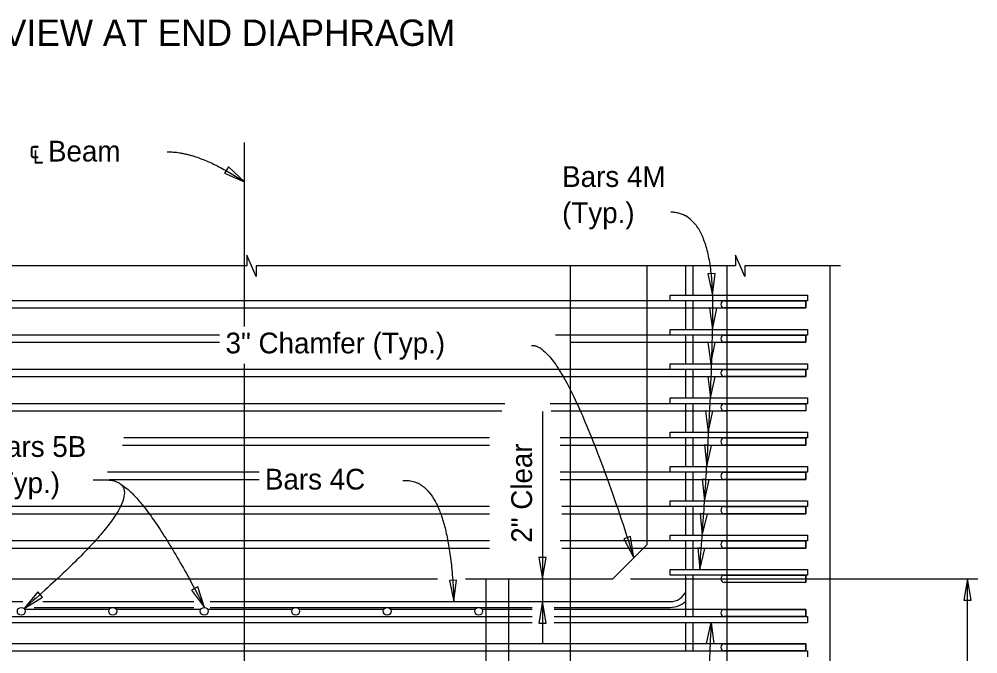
# Model space of a CAD drawing. Extents: x 120700.3 to 120754.4, y 120608.4 to 120631.3.
# Drawn here: x 120705.72 to 120712.71, y 120614.85 to 120619.48 of the extents above; entities that cross this region are included whole.
import ezdxf

# ---------------------------------------------------------------- set-up
doc = ezdxf.new("R2010")
doc.units = 0
for name, color, linetype in [('BeamConc', 7, 'Continuous'), ('BeamConc_h', 7, 'Continuous'), ('CL_Major', 7, 'Continuous'), ('Dimension', 7, 'Continuous'), ('Miscellaneous', 7, 'Continuous'), ('Rebar', 7, 'Continuous'), ('Rebar_h', 7, 'Continuous'), ('TextStructures', 7, 'Continuous')]:
    doc.layers.add(name, color=color, linetype=linetype)

msp = doc.modelspace()

# ---------------------------------------------------------------- linework, layer by layer
at = {"layer": 'BeamConc'}
for p, q in [((120710.3004, 120615.6485), (120710.3004, 120617.6787)), ((120711.6337, 120613.461), (120711.6337, 120617.6787)), ((120710.0504, 120615.3985), (120710.3004, 120615.6485)), ((120704.7587, 120615.3985), (120708.7707, 120615.3985)), ((120708.9744, 120615.3985), (120710.0504, 120615.3985))]:
    msp.add_line(p, q, dxfattribs=at)
at = {"layer": 'BeamConc_h'}
for p, q in [((120709.7379, 120617.6787), (120709.7379, 120613.3985)), ((120710.8837, 120613.461), (120710.8837, 120617.6787))]:
    msp.add_line(p, q, dxfattribs=at)
at = {"layer": 'CL_Major'}
for p, q in [((120707.3658, 120617.2362), (120707.3658, 120618.5791)), ((120707.3658, 120612.1032), (120707.3658, 120616.9656))]:
    msp.add_line(p, q, dxfattribs=at)
at = {"layer": 'Dimension'}
for p, q in [((120709.536, 120616.6175), (120709.536, 120614.9295)), ((120706.3787, 120616.1183), (120706.2624, 120616.1183)), ((120709.6116, 120615.3985), (120709.6116, 120615.3985)), ((120710.1779, 120615.3985), (120712.7094, 120615.3985)), ((120712.6337, 120613.3985), (120712.6337, 120615.3985)), ((120709.6116, 120615.2319), (120709.6116, 120615.2319))]:
    msp.add_line(p, q, dxfattribs=at)
for points in [[(120707.3637, 120618.2906), (120707.2488, 120618.3996), (120707.2193, 120618.3556)], [(120710.7765, 120617.4662), (120710.7944, 120617.6237), (120710.7415, 120617.6208)], [(120710.7761, 120617.2162), (120710.8072, 120617.3716), (120710.7543, 120617.3732)], [(120710.7637, 120616.9662), (120710.7948, 120617.1216), (120710.7419, 120617.1232)], [(120710.76, 120616.7162), (120710.7941, 120616.8709), (120710.7413, 120616.8736)], [(120710.7439, 120616.4662), (120710.778, 120616.6209), (120710.7252, 120616.6236)], [(120710.7339, 120616.2162), (120710.7693, 120616.3706), (120710.7165, 120616.3737)], [(120706.3658, 120616.1225), (120706.3658, 120616.1225)], [(120710.7169, 120615.9662), (120710.7524, 120616.1206), (120710.6995, 120616.1237)], [(120710.7006, 120615.7162), (120710.7388, 120615.87), (120710.686, 120615.874)], [(120710.203, 120615.551), (120710.1784, 120615.7075), (120710.1282, 120615.6907)], [(120710.6822, 120615.4657), (120710.7204, 120615.6195), (120710.6676, 120615.6235)], [(120709.536, 120615.3984), (120709.5627, 120615.5541), (120709.5093, 120615.5541)], [(120708.8908, 120615.2318), (120708.911, 120615.3889), (120708.8581, 120615.3868)], [(120712.6337, 120615.3985), (120712.607, 120615.2428), (120712.6604, 120615.2428)], [(120707.0737, 120615.1901), (120707.0254, 120615.3409), (120706.9784, 120615.3166)], [(120705.7584, 120615.1815), (120705.8937, 120615.2638), (120705.8591, 120615.3038)], [(120709.536, 120615.2318), (120709.5093, 120615.0761), (120709.5627, 120615.0761)], [(120710.7651, 120615.0808), (120710.7848, 120614.9236), (120710.732, 120614.9259)]]:
    msp.add_lwpolyline(points, close=True, dxfattribs=at)
for points in [[(120710.2248, 120617.6787), (120707.4487, 120617.6787), (120707.4487, 120617.6012), (120707.4149, 120617.6787), (120707.3812, 120617.7562), (120707.3812, 120617.6787), (120704.5843, 120617.6787)], [(120711.7093, 120617.6787), (120711.0101, 120617.6787), (120711.0101, 120617.6012), (120710.9763, 120617.6787), (120710.9426, 120617.7562), (120710.9426, 120617.6787), (120710.2248, 120617.6787)]]:
    msp.add_lwpolyline(points, dxfattribs=at)
for points in [[(120706.8012, 120618.5108), (120707.0356, 120618.5108), (120707.3637, 120618.2906)], [(120710.6826, 120615.4663), (120710.7724, 120616.6527), (120710.7836, 120618.0663), (120710.4714, 120618.0701)], [(120709.4568, 120617.0994), (120709.7035, 120617.1144), (120710.203, 120615.551)], [(120706.4625, 120616.0887), (120706.6316, 120615.9385), (120705.7584, 120615.1816)], [(120706.3787, 120616.1183), (120706.5935, 120616.1183), (120707.0737, 120615.1901)], [(120708.5177, 120616.1149), (120708.8579, 120616.1414), (120708.8908, 120615.2319)], [(120710.7651, 120615.0808), (120710.7175, 120613.9747), (120710.73, 120612.9136), (120710.8986, 120612.9448)]]:
    msp.add_open_spline(points, degree=2, dxfattribs=at)
at = {"layer": 'Miscellaneous'}
for p, q in [((120709.1225, 120615.3985), (120709.1225, 120613.3985)), ((120709.2892, 120615.3985), (120709.2892, 120613.3985))]:
    msp.add_line(p, q, dxfattribs=at)
at = {"layer": 'Rebar'}
for p, q in [((120710.5817, 120617.4663), (120710.5817, 120617.6787)), ((120710.6337, 120617.4663), (120710.6337, 120617.6787)), ((120710.467, 120617.4663), (120711.4671, 120617.4663)), ((120710.467, 120617.4246), (120710.467, 120617.4663)), ((120711.4671, 120617.4246), (120710.467, 120617.4246)), ((120710.5817, 120617.2163), (120710.5817, 120617.4246)), ((120710.6337, 120617.2163), (120710.6337, 120617.4246)), ((120710.8617, 120617.4246), (120711.4557, 120617.4246)), ((120711.4557, 120617.4246), (120711.4557, 120617.3725)), ((120711.4671, 120617.4663), (120711.4671, 120617.4246)), ((120711.4557, 120617.3725), (120710.8617, 120617.3725)), ((120710.467, 120617.2163), (120711.4671, 120617.2163)), ((120710.467, 120617.1746), (120710.467, 120617.2163)), ((120711.4671, 120617.2163), (120711.4671, 120617.1746)), ((120711.4671, 120617.1746), (120710.467, 120617.1746)), ((120710.5817, 120616.9663), (120710.5817, 120617.1746)), ((120710.6337, 120616.9663), (120710.6337, 120617.1746)), ((120710.8617, 120617.1746), (120711.4557, 120617.1746)), ((120711.4557, 120617.1746), (120711.4557, 120617.1225)), ((120711.4557, 120617.1225), (120710.8617, 120617.1225)), ((120710.467, 120616.9663), (120711.4671, 120616.9663)), ((120710.467, 120616.9246), (120710.467, 120616.9663)), ((120711.4671, 120616.9246), (120710.467, 120616.9246)), ((120710.5817, 120616.7163), (120710.5817, 120616.9246)), ((120710.6337, 120616.7163), (120710.6337, 120616.9246)), ((120710.8617, 120616.9246), (120711.4557, 120616.9246)), ((120711.4557, 120616.9246), (120711.4557, 120616.8725)), ((120711.4671, 120616.9663), (120711.4671, 120616.9246)), ((120711.4557, 120616.8725), (120710.8617, 120616.8725)), ((120710.467, 120616.7163), (120711.4671, 120616.7163)), ((120710.467, 120616.6746), (120710.467, 120616.7163)), ((120711.4671, 120616.7163), (120711.4671, 120616.6746)), ((120711.4671, 120616.6746), (120710.467, 120616.6746)), ((120710.5817, 120616.4663), (120710.5817, 120616.6746)), ((120710.6337, 120616.4663), (120710.6337, 120616.6746)), ((120710.8617, 120616.6746), (120711.4557, 120616.6746)), ((120711.4557, 120616.6746), (120711.4557, 120616.6225)), ((120711.4557, 120616.6225), (120710.8617, 120616.6225)), ((120710.467, 120616.4663), (120711.4671, 120616.4663)), ((120710.467, 120616.4246), (120710.467, 120616.4663)), ((120711.4671, 120616.4663), (120711.4671, 120616.4246)), ((120711.4671, 120616.4246), (120710.467, 120616.4246)), ((120710.5817, 120616.2163), (120710.5817, 120616.4246)), ((120710.6337, 120616.2163), (120710.6337, 120616.4246)), ((120710.8617, 120616.4246), (120711.4557, 120616.4246)), ((120711.4557, 120616.3725), (120710.8617, 120616.3725)), ((120711.4557, 120616.4246), (120711.4557, 120616.3725)), ((120710.467, 120616.2163), (120711.4671, 120616.2163)), ((120710.467, 120616.1746), (120710.467, 120616.2163)), ((120711.4671, 120616.1746), (120710.467, 120616.1746)), ((120710.5817, 120615.9663), (120710.5817, 120616.1746)), ((120710.6337, 120615.9663), (120710.6337, 120616.1746)), ((120710.8617, 120616.1746), (120711.4557, 120616.1746)), ((120711.4557, 120616.1746), (120711.4557, 120616.1225)), ((120711.4671, 120616.2163), (120711.4671, 120616.1746)), ((120711.4557, 120616.1225), (120710.8617, 120616.1225)), ((120710.467, 120615.9663), (120711.4671, 120615.9663)), ((120710.467, 120615.9246), (120710.467, 120615.9663)), ((120711.4671, 120615.9663), (120711.4671, 120615.9246)), ((120711.4671, 120615.9246), (120710.467, 120615.9246)), ((120710.5817, 120615.7163), (120710.5817, 120615.9246)), ((120710.6337, 120615.7163), (120710.6337, 120615.9246)), ((120710.8617, 120615.9246), (120711.4557, 120615.9246)), ((120711.4557, 120615.9246), (120711.4557, 120615.8725)), ((120711.4557, 120615.8725), (120710.8617, 120615.8725)), ((120710.467, 120615.7163), (120711.4671, 120615.7163)), ((120710.467, 120615.6746), (120710.467, 120615.7163)), ((120711.4671, 120615.6746), (120710.467, 120615.6746)), ((120710.5817, 120615.4663), (120710.5817, 120615.6746)), ((120710.6337, 120615.4663), (120710.6337, 120615.6746)), ((120710.8617, 120615.6746), (120711.4557, 120615.6746)), ((120711.4557, 120615.6746), (120711.4557, 120615.6225)), ((120711.4671, 120615.7163), (120711.4671, 120615.6746)), ((120711.4557, 120615.6225), (120710.8617, 120615.6225)), ((120710.467, 120615.4663), (120711.4671, 120615.4663)), ((120710.467, 120615.4246), (120710.467, 120615.4663)), ((120711.4671, 120615.4663), (120711.4671, 120615.4246)), ((120711.4671, 120615.4246), (120710.467, 120615.4246)), ((120710.5817, 120615.1225), (120710.5817, 120615.4246)), ((120710.6337, 120615.1225), (120710.6337, 120615.4246)), ((120710.8617, 120615.4246), (120711.4557, 120615.4246)), ((120711.4557, 120615.4246), (120711.4557, 120615.3725)), ((120711.4557, 120615.3725), (120710.8617, 120615.3725)), ((120704.3421, 120615.2319), (120705.7483, 120615.2319)), ((120705.832, 120615.1902), (120706.9949, 120615.1902)), ((120705.8943, 120615.2319), (120706.9949, 120615.2319)), ((120707.1139, 120615.2319), (120710.4671, 120615.2319)), ((120707.1139, 120615.1902), (120709.4623, 120615.1902)), ((120709.6223, 120615.1902), (120710.4669, 120615.1902)), ((120703.3421, 120615.1225), (120709.4623, 120615.1225)), ((120709.6223, 120615.1225), (120711.4671, 120615.1225)), ((120710.8617, 120615.1746), (120711.4557, 120615.1746)), ((120711.4557, 120615.1225), (120710.8617, 120615.1225)), ((120711.4557, 120615.1746), (120711.4557, 120615.1225)), ((120711.4671, 120615.1225), (120711.4671, 120615.0808)), ((120703.3421, 120615.0808), (120709.4623, 120615.0808)), ((120709.6223, 120615.0808), (120711.4671, 120615.0808)), ((120710.5817, 120614.8725), (120710.5817, 120615.0808)), ((120710.6337, 120614.8725), (120710.6337, 120615.0808)), ((120710.8617, 120614.9246), (120711.4557, 120614.9246)), ((120711.4557, 120614.9246), (120711.4557, 120614.8725)), ((120703.3421, 120614.8725), (120711.4671, 120614.8725)), ((120711.4557, 120614.8725), (120710.8617, 120614.8725)), ((120711.4671, 120614.8725), (120711.4671, 120614.8308))]:
    msp.add_line(p, q, dxfattribs=at)
for centre in [(120705.7379, 120615.1615), (120706.4046, 120615.1615), (120707.0712, 120615.1615), (120707.7379, 120615.1615), (120708.4046, 120615.1615), (120709.0712, 120615.1615)]:
    msp.add_circle(centre, 0.0287, dxfattribs=at)
for centre, radius, start, end in [((120710.8617, 120617.3986), 0.026, 90, 270), ((120710.8617, 120617.1486), 0.026, 90, 270), ((120710.8617, 120616.8986), 0.026, 90, 270), ((120710.8617, 120616.6486), 0.026, 90, 270), ((120710.8617, 120616.3986), 0.026, 90, 270), ((120710.8617, 120616.1486), 0.026, 90, 270), ((120710.8617, 120615.8986), 0.026, 90, 270), ((120710.8617, 120615.6486), 0.026, 90, 270), ((120710.8617, 120615.3986), 0.026, 90, 270), ((120710.467, 120615.3569), 0.125, 270, 336.48194), ((120710.4671, 120615.3569), 0.1667, 270, 313.43255), ((120710.8617, 120615.1486), 0.026, 90, 270), ((120710.8617, 120614.8986), 0.026, 90, 270)]:
    msp.add_arc(centre, radius, start, end, dxfattribs=at)
at = {"layer": 'Rebar_h'}
msp.add_line((120711.4557, 120615.3725), (120711.4557, 120615.4246), dxfattribs=at)
for points in [[(120711.4557, 120617.4246), (120703.3535, 120617.4246), (120703.3535, 120617.3725), (120711.4557, 120617.3725)], [(120711.4557, 120616.9246), (120703.3535, 120616.9246), (120703.3535, 120616.8725), (120711.4557, 120616.8725)]]:
    msp.add_lwpolyline(points, close=True, dxfattribs=at)
for points in [[(120707.1823, 120617.1746), (120703.3535, 120617.1746), (120703.3535, 120617.1225), (120707.1823, 120617.1225)], [(120709.737, 120617.1225), (120711.4557, 120617.1225), (120711.4557, 120617.1746), (120709.6308, 120617.1746)], [(120709.2631, 120616.6746), (120703.3535, 120616.6746), (120703.3535, 120616.6225), (120709.2394, 120616.6225)], [(120710.467, 120616.6746), (120709.5935, 120616.6746)], [(120709.6007, 120616.6225), (120710.8837, 120616.6225)], [(120706.476, 120616.3725), (120709.1503, 120616.3725)], [(120709.1503, 120616.4246), (120706.486, 120616.4246)], [(120709.6647, 120616.3725), (120711.4557, 120616.3725), (120711.4557, 120616.4246), (120709.6647, 120616.4246)], [(120707.471, 120616.1746), (120706.3658, 120616.1746)], [(120709.6647, 120616.1225), (120711.4557, 120616.1225), (120711.4557, 120616.1746), (120709.6647, 120616.1746)], [(120706.3804, 120616.1225), (120707.471, 120616.1225)], [(120709.1503, 120615.9246), (120703.3535, 120615.9246), (120703.3535, 120615.8725), (120709.1503, 120615.8725)], [(120709.6768, 120615.8725), (120711.4557, 120615.8725), (120711.4557, 120615.9246), (120709.6768, 120615.9246)], [(120709.1503, 120615.6746), (120703.3535, 120615.6746), (120703.3535, 120615.6225), (120709.1503, 120615.6225)], [(120709.6768, 120615.6225), (120711.4557, 120615.6225), (120711.4557, 120615.6746), (120709.6647, 120615.6746)], [(120706.3807, 120615.1746), (120705.7618, 120615.1746)], [(120705.7639, 120615.1225), (120706.3785, 120615.1225)], [(120707.0474, 120615.1746), (120706.4284, 120615.1746)], [(120706.4306, 120615.1225), (120707.0452, 120615.1225)], [(120707.714, 120615.1746), (120707.0951, 120615.1746)], [(120707.0973, 120615.1225), (120707.7119, 120615.1225)], [(120708.3807, 120615.1746), (120707.7618, 120615.1746)], [(120707.764, 120615.1225), (120708.3785, 120615.1225)], [(120709.0474, 120615.1746), (120708.4285, 120615.1746)], [(120708.4306, 120615.1225), (120709.0452, 120615.1225)], [(120709.4623, 120615.1746), (120709.0951, 120615.1746)], [(120709.0973, 120615.1225), (120709.4623, 120615.1225)], [(120709.6223, 120615.1225), (120711.4557, 120615.1225), (120711.4557, 120615.1746), (120709.6223, 120615.1746)], [(120710.484, 120614.9246), (120703.3535, 120614.9246), (120703.3535, 120614.8725), (120705.7119, 120614.8725)], [(120709.0973, 120614.8725), (120711.4557, 120614.8725), (120711.4557, 120614.9246), (120710.484, 120614.9246)]]:
    msp.add_lwpolyline(points, dxfattribs=at)

# ---------------------------------------------------------------- texts
at = {"layer": 'Dimension'}
for s, p in [('Bars 4M', (120709.6799, 120618.2543)), ('(Typ.)', (120709.6799, 120617.9903))]:
    msp.add_text(s, height=0.1512, dxfattribs=at).set_placement(p)
at = {"layer": 'TextStructures'}
for s, height, p in [('END VIEW AT END DIAPHRAGM', 0.192, (120704.9916, 120619.2821)), ('℄ Beam', 0.1512, (120705.7944, 120618.4396)), ('3" Chamfer (Typ.)', 0.1512, (120707.2267, 120617.0412)), ('Bars 5B', 0.1512, (120705.4922, 120616.2868)), ('(Typ.)', 0.1512, (120705.4922, 120616.0228)), ('Bars 4C', 0.1512, (120707.5138, 120616.049))]:
    msp.add_text(s, height=height, dxfattribs=at).set_placement(p)
msp.add_text('2" Clear', height=0.1512, rotation=90, dxfattribs=at).set_placement((120709.4604, 120615.6614))

doc.saveas('drawing.dxf')
